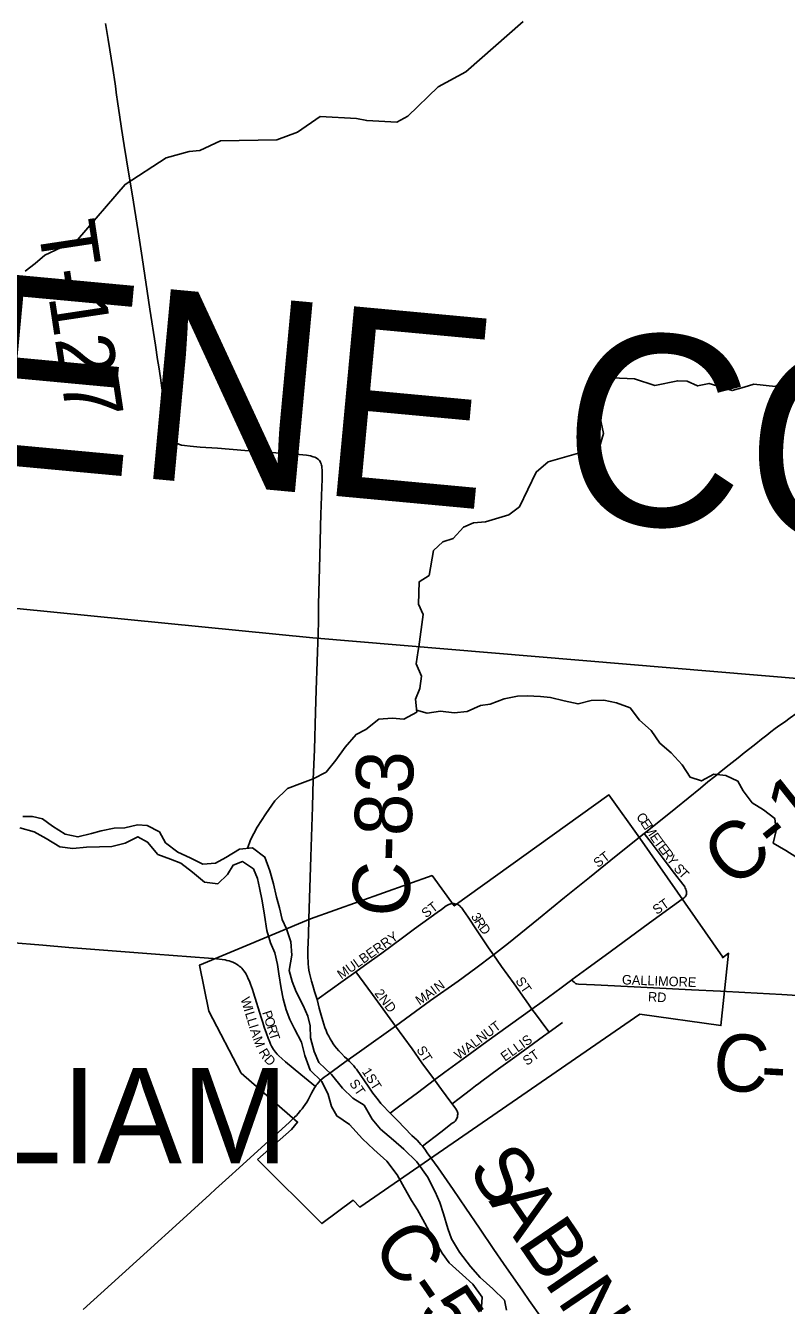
# Model space of a CAD drawing. Extents: x -49 to -8.2, y 9.4 to 23.5.
# Drawn here: x -45.924 to -45.546, y 15.045 to 15.681 of the extents above; entities that cross this region are included whole.
import ezdxf

# ---------------------------------------------------------------- set-up
doc = ezdxf.new("R2010")
doc.units = 0
for name, color, linetype in [('GM_X_Adjacent_County', 7, 'Continuous'), ('GM_X_Adjacent_County_Text', 7, 'Continuous'), ('GM_X_City_Street', 7, 'Continuous'), ('GM_X_City_Street_Text', 7, 'Continuous'), ('GM_X_Corporation', 7, 'Continuous'), ('GM_X_Corporation_Text', 7, 'Continuous'), ('GM_X_County_Road', 7, 'Continuous'), ('GM_X_County_Road_Text', 7, 'Continuous'), ('GM_X_Major_River', 7, 'Continuous'), ('GM_X_Minor_River', 7, 'Continuous'), ('GM_X_State_Route', 7, 'Continuous'), ('GM_X_Township', 7, 'Continuous'), ('GM_X_Township_Road', 7, 'Continuous'), ('GM_X_Township_Road_Text', 7, 'Continuous')]:
    doc.layers.add(name, color=color, linetype=linetype)

msp = doc.modelspace()

# ---------------------------------------------------------------- linework, layer by layer
at = {"layer": 'GM_X_Adjacent_County'}
msp.add_lwpolyline([(-46.28954, 15.42735), (-46.27406, 15.42591), (-46.16919, 15.41553), (-45.78121, 15.37701), (-45.51504, 15.35475), (-44.76178, 15.2786), (-44.52941, 15.25783), (-44.16568, 15.22458), (-44.06357, 15.21525), (-43.87916, 15.1984), (-43.71722, 15.18325)], dxfattribs=at)
at = {"layer": 'GM_X_City_Street'}
for points in [[(-45.6916, 15.21959), (-45.68413, 15.22528), (-45.66921, 15.23738), (-45.65625, 15.24803), (-45.64387, 15.25793), (-45.63065, 15.26869), (-45.61669, 15.2799)], [(-45.59564, 15.2497), (-45.5956, 15.25034), (-45.59568, 15.25096), (-45.59581, 15.25157), (-45.59601, 15.25219), (-45.59626, 15.25272), (-45.59654, 15.25326), (-45.59683, 15.25375), (-45.59743, 15.25462), (-45.60153, 15.26001), (-45.60717, 15.26748), (-45.61315, 15.27541), (-45.61669, 15.2799)], [(-45.65256, 15.20716), (-45.6524, 15.20728), (-45.64514, 15.21262), (-45.63359, 15.22104), (-45.61407, 15.23537), (-45.59787, 15.24715), (-45.59688, 15.24789), (-45.59633, 15.24838), (-45.59597, 15.2488), (-45.59577, 15.24921), (-45.59564, 15.2497)], [(-45.75994, 15.21109), (-45.75561, 15.21423), (-45.74705, 15.22043), (-45.73679, 15.22798), (-45.73078, 15.23239), (-45.71957, 15.24056), (-45.7174, 15.24212), (-45.71499, 15.24382), (-45.71433, 15.24423), (-45.71379, 15.24452), (-45.71326, 15.24477), (-45.71277, 15.24493), (-45.71234, 15.245), (-45.71181, 15.24504), (-45.71123, 15.24504), (-45.71066, 15.24496)], [(-45.6916, 15.21959), (-45.69395, 15.22297), (-45.69968, 15.23144), (-45.70409, 15.23821), (-45.70635, 15.24156), (-45.70704, 15.24249), (-45.70733, 15.24286), (-45.7077, 15.24327), (-45.70823, 15.24381), (-45.70876, 15.24422), (-45.70926, 15.24451), (-45.70987, 15.24475), (-45.71066, 15.24496)], [(-45.77918, 15.19728), (-45.78038, 15.20125), (-45.78132, 15.20433), (-45.78194, 15.20647), (-45.78231, 15.20778), (-45.78264, 15.20914), (-45.78297, 15.21049), (-45.78326, 15.21189), (-45.78344, 15.21343), (-45.78359, 15.21506), (-45.78367, 15.2165), (-45.7837, 15.21781), (-45.78371, 15.21991), (-45.78371, 15.22217), (-45.78349, 15.22933), (-45.7833, 15.23742)], [(-45.8331, 15.21781), (-45.83084, 15.21767), (-45.82911, 15.21754), (-45.82627, 15.21721), (-45.82487, 15.21697), (-45.82392, 15.21677), (-45.82286, 15.21648), (-45.82196, 15.21619), (-45.82097, 15.21582), (-45.82031, 15.21553), (-45.81974, 15.21524), (-45.81916, 15.21491), (-45.81842, 15.21442), (-45.81781, 15.21397), (-45.81711, 15.21339), (-45.81657, 15.21286), (-45.81601, 15.21222), (-45.8155, 15.21154), (-45.81497, 15.21076), (-45.81447, 15.20998), (-45.81392, 15.20901), (-45.81333, 15.20768), (-45.81276, 15.20642), (-45.81222, 15.20501), (-45.81168, 15.20357), (-45.81124, 15.20231), (-45.81069, 15.20065), (-45.80693, 15.18833), (-45.80613, 15.18585), (-45.80539, 15.18355), (-45.80434, 15.18038), (-45.8035, 15.17809), (-45.80268, 15.17605), (-45.80227, 15.17509), (-45.80182, 15.17414), (-45.80136, 15.17332), (-45.80087, 15.17255), (-45.80038, 15.17188), (-45.79977, 15.17112), (-45.79894, 15.17024), (-45.7981, 15.16934), (-45.79672, 15.16806), (-45.79491, 15.16641), (-45.78728, 15.16006), (-45.78365, 15.15712), (-45.77998, 15.15413)], [(-45.74021, 15.18415), (-45.73276, 15.1895), (-45.72275, 15.19689), (-45.70902, 15.20652), (-45.70026, 15.21298), (-45.6916, 15.21959)], [(-45.6724, 15.1926), (-45.67416, 15.19502), (-45.68127, 15.20505), (-45.68747, 15.21376), (-45.6916, 15.21959)], [(-45.77918, 15.19728), (-45.7662, 15.20657), (-45.75994, 15.21109)], [(-45.74021, 15.18415), (-45.7516, 15.19988), (-45.75808, 15.2086), (-45.75994, 15.21109)], [(-45.6724, 15.1926), (-45.66738, 15.19623), (-45.65786, 15.20316), (-45.65256, 15.20716)], [(-45.65256, 15.20716), (-45.65204, 15.20651), (-45.65151, 15.20593), (-45.65114, 15.20556), (-45.65077, 15.20532), (-45.65031, 15.20515), (-45.64933, 15.20499), (-45.64127, 15.20464), (-45.6183, 15.20346), (-45.59314, 15.20214), (-45.57867, 15.20141)], [(-45.76377, 15.16728), (-45.76549, 15.16888), (-45.76709, 15.17048), (-45.76837, 15.17184), (-45.76948, 15.17312), (-45.77034, 15.17419), (-45.77115, 15.1753), (-45.7719, 15.17644), (-45.77265, 15.17772), (-45.77338, 15.17903), (-45.77408, 15.18043), (-45.7747, 15.18187), (-45.7753, 15.18345), (-45.77585, 15.18507), (-45.77637, 15.18674), (-45.77721, 15.18947), (-45.77811, 15.19301), (-45.77918, 15.19728)], [(-45.72086, 15.15736), (-45.71568, 15.1612), (-45.70481, 15.16921), (-45.69483, 15.17638), (-45.6724, 15.1926)], [(-45.66394, 15.18105), (-45.66556, 15.18326), (-45.67015, 15.18952), (-45.6724, 15.1926)], [(-45.76377, 15.16728), (-45.757, 15.17211), (-45.74021, 15.18415)], [(-45.72086, 15.15736), (-45.72707, 15.16593), (-45.73191, 15.17277), (-45.74021, 15.18415)], [(-45.66394, 15.18105), (-45.65718, 15.18598)], [(-45.71205, 15.1454), (-45.70855, 15.14808), (-45.7029, 15.15241), (-45.7004, 15.15437), (-45.6988, 15.1556), (-45.69725, 15.15674), (-45.68901, 15.16281), (-45.68098, 15.16862), (-45.6667, 15.17903), (-45.66394, 15.18105)], [(-45.77998, 15.15413), (-45.77958, 15.1547), (-45.77913, 15.15532), (-45.77837, 15.15623), (-45.77759, 15.15705), (-45.77665, 15.15788), (-45.77565, 15.15867), (-45.77418, 15.15977), (-45.76536, 15.16615), (-45.76377, 15.16728)], [(-45.76377, 15.16728), (-45.76303, 15.16658), (-45.76221, 15.16576), (-45.76151, 15.16502), (-45.76089, 15.16432), (-45.76017, 15.16335), (-45.75966, 15.16264), (-45.75344, 15.15374), (-45.75144, 15.15084), (-45.75021, 15.14913), (-45.74889, 15.14739), (-45.7475, 15.14568), (-45.74591, 15.14393), (-45.74406, 15.14204), (-45.74287, 15.14084)], [(-45.79037, 15.13877), (-45.78947, 15.13971), (-45.78854, 15.1407), (-45.78733, 15.14209), (-45.78659, 15.143), (-45.78585, 15.14398), (-45.78503, 15.14515), (-45.78433, 15.14629), (-45.78363, 15.14752), (-45.78281, 15.14908), (-45.78191, 15.15073), (-45.78109, 15.15224), (-45.78047, 15.15335), (-45.77998, 15.15413)], [(-45.74287, 15.14084), (-45.74007, 15.14293), (-45.73427, 15.14726), (-45.72926, 15.151), (-45.72086, 15.15736)], [(-45.71205, 15.1454), (-45.71279, 15.14638), (-45.71741, 15.1526), (-45.72086, 15.15736)], [(-45.72683, 15.12451), (-45.71768, 15.13141), (-45.71198, 15.13579), (-45.71114, 15.13643), (-45.71061, 15.13692), (-45.71015, 15.1375), (-45.70987, 15.13799), (-45.70962, 15.13853), (-45.70945, 15.13906), (-45.70935, 15.13977), (-45.70929, 15.14034), (-45.70928, 15.14091), (-45.70937, 15.14136), (-45.70954, 15.14177), (-45.70975, 15.14219), (-45.71024, 15.14292), (-45.71076, 15.14367), (-45.71205, 15.1454)], [(-45.74287, 15.14084), (-45.74198, 15.13995), (-45.73901, 15.13695), (-45.73573, 15.13358), (-45.73202, 15.1298)], [(-45.73202, 15.1298), (-45.72951, 15.12734), (-45.72837, 15.12619), (-45.72754, 15.12532), (-45.72683, 15.12451)]]:
    msp.add_lwpolyline(points, dxfattribs=at)
at = {"layer": 'GM_X_Corporation'}
msp.add_lwpolyline([(-45.80878, 15.11774), (-45.79184, 15.13269), (-45.78888, 15.13638), (-45.81682, 15.16078), (-45.8329, 15.19151), (-45.83755, 15.2144), (-45.78239, 15.23744), (-45.72203, 15.25896), (-45.71105, 15.24384), (-45.63422, 15.29901), (-45.61886, 15.27749), (-45.57766, 15.21829), (-45.5777, 15.21809), (-45.57476, 15.22029), (-45.57857, 15.18434), (-45.61881, 15.19), (-45.75795, 15.09414), (-45.76123, 15.09752), (-45.77678, 15.08598)], close=True, dxfattribs=at)
at = {"layer": 'GM_X_County_Road'}
for points in [[(-45.7833, 15.23742), (-45.78229, 15.2682), (-45.78151, 15.29304), (-45.78104, 15.30669), (-45.7805, 15.32157), (-45.77996, 15.34017), (-45.77962, 15.35102), (-45.77913, 15.36529), (-45.77863, 15.37956)], [(-45.61669, 15.2799), (-45.60698, 15.28761), (-45.60102, 15.29247), (-45.58869, 15.30241), (-45.58496, 15.30546), (-45.58154, 15.30821), (-45.57834, 15.31076), (-45.57441, 15.31393), (-45.56995, 15.3175), (-45.56691, 15.31992), (-45.56422, 15.32205), (-45.56124, 15.3244), (-45.5584, 15.32666), (-45.55571, 15.32878), (-45.55372, 15.33032), (-45.55154, 15.33198), (-45.54928, 15.33361), (-45.54702, 15.33525), (-45.54414, 15.33731), (-45.54135, 15.33928), (-45.53814, 15.3415), (-45.53382, 15.34442), (-45.52501, 15.35028), (-45.51027, 15.36047)], [(-45.93186, 15.2257), (-45.91545, 15.22431), (-45.90245, 15.22321), (-45.85938, 15.21988), (-45.8331, 15.21781)], [(-45.57867, 15.20141), (-45.56666, 15.2008), (-45.54821, 15.19974), (-45.51486, 15.19773)], [(-45.72683, 15.12451), (-45.72569, 15.12298), (-45.72442, 15.12113), (-45.71898, 15.11363), (-45.71152, 15.10294), (-45.70531, 15.09364), (-45.69844, 15.08365), (-45.6913, 15.07311), (-45.68662, 15.06614), (-45.67701, 15.05239), (-45.67379, 15.04781), (-45.66774, 15.03917)]]:
    msp.add_lwpolyline(points, dxfattribs=at)
at = {"layer": 'GM_X_Major_River'}
for points in [[(-45.71421, 15.08358), (-45.71628, 15.09079), (-45.71816, 15.09649), (-45.72043, 15.1018), (-45.72439, 15.10921), (-45.72968, 15.11661), (-45.73611, 15.12288), (-45.74122, 15.12744), (-45.74765, 15.13295), (-45.75181, 15.13789), (-45.75578, 15.14473), (-45.76146, 15.14834), (-45.76656, 15.15328), (-45.77205, 15.16012), (-45.77829, 15.16601), (-45.78055, 15.17151), (-45.78243, 15.17834), (-45.78261, 15.18423), (-45.78374, 15.18897), (-45.786, 15.19429), (-45.78959, 15.20112), (-45.79148, 15.20625), (-45.79298, 15.21175), (-45.79165, 15.21933), (-45.7922, 15.22597), (-45.79428, 15.23243), (-45.79654, 15.23717), (-45.79786, 15.24287), (-45.79936, 15.24818), (-45.80087, 15.25482), (-45.80256, 15.26128), (-45.8052, 15.26811), (-45.81126, 15.27267), (-45.8177, 15.27211), (-45.82453, 15.26795), (-45.82965, 15.26511), (-45.8359, 15.26455), (-45.84214, 15.26779), (-45.84839, 15.27064), (-45.85444, 15.27521), (-45.85747, 15.28071), (-45.86352, 15.28376), (-45.86845, 15.28414), (-45.8747, 15.28264), (-45.88001, 15.28245), (-45.88645, 15.28114), (-45.89119, 15.27982), (-45.89801, 15.27812), (-45.90426, 15.27946), (-45.91069, 15.28345), (-45.91561, 15.28706), (-45.92054, 15.28821), (-45.92527, 15.28822)], [(-45.9268, 15.28272), (-45.91979, 15.28062), (-45.91374, 15.27739), (-45.90692, 15.2732), (-45.90048, 15.27243), (-45.89366, 15.27299), (-45.88722, 15.27317), (-45.88116, 15.27335), (-45.87453, 15.27505), (-45.86827, 15.27826), (-45.86335, 15.2756), (-45.85824, 15.26933), (-45.852, 15.26704), (-45.84688, 15.26514), (-45.84102, 15.26058), (-45.83516, 15.25564), (-45.82853, 15.25487), (-45.82359, 15.25941), (-45.82093, 15.26415), (-45.81619, 15.26585), (-45.81071, 15.26224), (-45.80882, 15.25749), (-45.80769, 15.25275), (-45.80638, 15.24629), (-45.80525, 15.23927), (-45.80413, 15.23168), (-45.80224, 15.22542), (-45.80017, 15.22049), (-45.79885, 15.21479), (-45.7981, 15.21005), (-45.79698, 15.20284), (-45.79604, 15.19772), (-45.79453, 15.19221), (-45.79265, 15.18747), (-45.79038, 15.18272), (-45.78698, 15.17608), (-45.78529, 15.16943), (-45.78265, 15.16222), (-45.77679, 15.15652), (-45.77358, 15.15007), (-45.77207, 15.14418), (-45.76943, 15.13944), (-45.76299, 15.13525), (-45.75657, 15.12804), (-45.75089, 15.12272), (-45.74446, 15.11701), (-45.73936, 15.11018), (-45.73596, 15.10391), (-45.73218, 15.09746), (-45.72935, 15.09271), (-45.7267, 15.08796), (-45.72349, 15.08227)], [(-45.72349, 15.08227), (-45.72066, 15.07752), (-45.71707, 15.07126), (-45.71348, 15.06651), (-45.70686, 15.06043), (-45.70175, 15.05587), (-45.69722, 15.04941), (-45.69761, 15.04221)], [(-45.6851, 15.04294), (-45.68604, 15.04788), (-45.69191, 15.05358), (-45.69815, 15.05909), (-45.70287, 15.0646), (-45.70835, 15.07181), (-45.71232, 15.07846), (-45.71421, 15.08358)]]:
    msp.add_lwpolyline(points, dxfattribs=at)
at = {"layer": 'GM_X_Minor_River'}
for points in [[(-45.92421, 15.55925), (-45.91924, 15.56317), (-45.91445, 15.56729), (-45.89824, 15.57486), (-45.87458, 15.60247), (-45.85413, 15.61569), (-45.84271, 15.61877), (-45.8374, 15.61927), (-45.8271, 15.62407), (-45.79921, 15.62466), (-45.78893, 15.62833), (-45.77764, 15.63616), (-45.75964, 15.63516), (-45.75453, 15.63415), (-45.73955, 15.63338), (-45.73402, 15.63635), (-45.71905, 15.65097), (-45.70531, 15.65839), (-45.67675, 15.68346)], [(-45.72863, 15.37266), (-45.72653, 15.38861), (-45.72875, 15.39377), (-45.72842, 15.40497), (-45.72346, 15.40813), (-45.72141, 15.42045), (-45.71662, 15.42476), (-45.71148, 15.4264), (-45.70648, 15.43203), (-45.70152, 15.43425), (-45.69545, 15.43474), (-45.68384, 15.43819), (-45.67867, 15.44212), (-45.67031, 15.45948), (-45.66437, 15.46453), (-45.63887, 15.47179), (-45.63689, 15.47861), (-45.63905, 15.4887), (-45.63936, 15.49478), (-45.63853, 15.50028), (-45.63258, 15.50628), (-45.6214, 15.50575), (-45.61138, 15.50258), (-45.59998, 15.5049), (-45.59524, 15.50465), (-45.59014, 15.50231), (-45.58444, 15.50356), (-45.57291, 15.49999), (-45.56701, 15.50163), (-45.56226, 15.50308), (-45.55146, 15.50199), (-45.54036, 15.51059)], [(-45.81381, 15.27245), (-45.8123, 15.27674), (-45.80896, 15.28295), (-45.80467, 15.28953), (-45.8002, 15.29611), (-45.79383, 15.30227), (-45.78772, 15.30445), (-45.78104, 15.307), (-45.77472, 15.31032), (-45.76987, 15.31632), (-45.76521, 15.3227), (-45.75979, 15.32908), (-45.755, 15.33147), (-45.74846, 15.33668), (-45.74181, 15.33714), (-45.73613, 15.33667), (-45.72962, 15.34018), (-45.73026, 15.34665), (-45.72809, 15.35193), (-45.72722, 15.35799), (-45.72996, 15.36411), (-45.7289, 15.37075), (-45.72863, 15.37266)], [(-45.72971, 15.34117), (-45.7245, 15.33972), (-45.71785, 15.34056), (-45.71103, 15.33988), (-45.70456, 15.34054), (-45.69806, 15.34347), (-45.69312, 15.34415), (-45.68624, 15.3467), (-45.67958, 15.34811), (-45.67483, 15.34823), (-45.66819, 15.34793), (-45.66327, 15.34747), (-45.65647, 15.34584), (-45.64947, 15.34421), (-45.64299, 15.34601), (-45.63673, 15.3461), (-45.63049, 15.34486), (-45.6237, 15.34228), (-45.61906, 15.33613), (-45.61327, 15.3311), (-45.60882, 15.32476), (-45.60321, 15.31992), (-45.59781, 15.31394), (-45.59374, 15.3078), (-45.58827, 15.306), (-45.58214, 15.30932), (-45.57608, 15.30866), (-45.57006, 15.3059), (-45.56748, 15.30111), (-45.56303, 15.29515), (-45.5574, 15.29164), (-45.55178, 15.28737), (-45.55112, 15.28129), (-45.55256, 15.27504), (-45.54636, 15.27133), (-45.54129, 15.26821)]]:
    msp.add_lwpolyline(points, dxfattribs=at)
at = {"layer": 'GM_X_State_Route'}
for points in [[(-45.80497, 15.12535), (-45.79827, 15.13139), (-45.79491, 15.13446), (-45.79284, 15.13637), (-45.79037, 15.13877)], [(-45.83247, 15.10047), (-45.82966, 15.10309), (-45.82299, 15.10911), (-45.81788, 15.11363), (-45.80497, 15.12535)], [(-45.89541, 15.04325), (-45.88133, 15.05595), (-45.86364, 15.07204), (-45.84754, 15.08667), (-45.83247, 15.10047)]]:
    msp.add_lwpolyline(points, dxfattribs=at)
at = {"layer": 'GM_X_Township'}
for points in [[(-43.71722, 15.18325), (-43.87916, 15.1984), (-44.06357, 15.21525), (-44.16568, 15.22458), (-44.52941, 15.25783), (-44.76178, 15.2786), (-45.51504, 15.35475), (-45.78121, 15.37701), (-46.16919, 15.41553), (-46.12789, 16.02951), (-46.09848, 16.46651), (-46.04007, 16.96971), (-46.00808, 17.24521), (-45.75383, 17.22725), (-45.26756, 17.19288), (-44.90793, 17.16748), (-44.90785, 17.16872), (-44.88623, 17.44008), (-44.88572, 17.44739), (-44.35121, 17.40327), (-44.11998, 17.3857), (-43.53715, 17.34141)], [(-44.82058, 14.20392), (-44.15889, 15.08792), (-44.06357, 15.21525), (-44.16568, 15.22458), (-44.52941, 15.25783), (-44.76178, 15.2786), (-45.51504, 15.35475), (-45.78121, 15.37701), (-46.16919, 15.41553), (-46.27406, 15.42591), (-46.28954, 15.42735)]]:
    msp.add_lwpolyline(points, dxfattribs=at)
at = {"layer": 'GM_X_Township_Road'}
msp.add_lwpolyline([(-45.77863, 15.37956), (-45.77853, 15.38495), (-45.7784, 15.39371), (-45.77814, 15.40591), (-45.77781, 15.41771), (-45.77757, 15.42516), (-45.77726, 15.43884), (-45.7772, 15.44255), (-45.77695, 15.44783), (-45.77678, 15.45187), (-45.77666, 15.45604), (-45.7767, 15.46053), (-45.77674, 15.46163), (-45.77684, 15.46241), (-45.77694, 15.46296), (-45.77711, 15.46351), (-45.77739, 15.46419), (-45.7777, 15.46474), (-45.77803, 15.46522), (-45.77849, 15.46567), (-45.77891, 15.46603), (-45.77965, 15.46649), (-45.78033, 15.46683), (-45.78104, 15.46712), (-45.7825, 15.46754), (-45.78348, 15.46772), (-45.78438, 15.46784), (-45.78814, 15.46817), (-45.80201, 15.46923), (-45.80633, 15.46958), (-45.81502, 15.47026), (-45.82862, 15.47132), (-45.83722, 15.47191), (-45.84219, 15.47231), (-45.84499, 15.47262), (-45.8465, 15.4729), (-45.84753, 15.4732), (-45.84851, 15.47365), (-45.84934, 15.4742), (-45.85022, 15.47496), (-45.85088, 15.47574), (-45.85152, 15.4767), (-45.85194, 15.47752), (-45.85229, 15.47848), (-45.85262, 15.47959), (-45.85318, 15.48218), (-45.85434, 15.48908), (-45.85621, 15.50137), (-45.85696, 15.50629), (-45.85781, 15.51181), (-45.85839, 15.51549), (-45.85949, 15.52256), (-45.86221, 15.54037), (-45.86601, 15.5662), (-45.86807, 15.57909), (-45.87105, 15.59779), (-45.87266, 15.6076), (-45.87494, 15.62171), (-45.8763, 15.63031), (-45.87732, 15.63707), (-45.87814, 15.64248), (-45.8789, 15.64811), (-45.87918, 15.64995), (-45.87954, 15.65241), (-45.88069, 15.66009), (-45.88298, 15.67451), (-45.8836, 15.6785), (-45.88421, 15.68249)], dxfattribs=at)

# ---------------------------------------------------------------- texts
at = {"layer": 'GM_X_Adjacent_County_Text'}
msp.add_text('GREENE COUNTY', height=0.094697, rotation=354.68716, dxfattribs=at).set_placement((-46.22828, 15.49024))
at = {"layer": 'GM_X_City_Street_Text'}
for s, height, rotation, p in [('C', 0.00473, 303.71028, (-45.62083, 15.28823)), ('E', 0.00473, 303.72039, (-45.61875, 15.28511)), ('M', 0.00473, 303.68502, (-45.6169, 15.28234)), ('E', 0.00473, 304.67272, (-45.61408, 15.2781)), ('T', 0.00473, 306.67344, (-45.61208, 15.27521)), ('E', 0.00473, 307.14584, (-45.61006, 15.27251)), ('ST', 0.004735, 37.57346, (-45.63962, 15.26261)), ('R', 0.00473, 307.21065, (-45.60804, 15.26984)), ('Y', 0.00473, 307.18471, (-45.60577, 15.26686)), ('S', 0.00473, 309.88889, (-45.60235, 15.26235)), ('T', 0.00473, 314.37325, (-45.59994, 15.2595)), ('ST', 0.004735, 34.68728, (-45.61042, 15.2393)), ('ST', 0.004735, 37.57346, (-45.72504, 15.23761)), ('3', 0.00473, 302.15758, (-45.7029, 15.23862)), ('R', 0.00473, 302.6636, (-45.70132, 15.23611)), ('D', 0.00473, 308.35058, (-45.699, 15.23254)), ('MULBERRY', 0.004735, 35.28861, (-45.76708, 15.20722)), ('GALLIMORE', 0.004735, 357.90998, (-45.62778, 15.20487)), ('2ND', 0.004735, 307.30709, (-45.75086, 15.20035)), ('I', 0.00473, 36.33162, (-45.7206, 15.19965)), ('N', 0.00473, 36.38522, (-45.71892, 15.20089)), ('ST', 0.004735, 304.69079, (-45.68084, 15.20657)), ('W', 0.00473, 287.11139, (-45.81726, 15.19768)), ('M', 0.00473, 33.89215, (-45.72831, 15.19431)), ('A', 0.00473, 35.64664, (-45.72403, 15.19719)), ('RD', 0.004735, 356.98902, (-45.61487, 15.19641)), ('I', 0.00473, 287.09309, (-45.81566, 15.19251)), ('L', 0.00473, 287.12197, (-45.81505, 15.19051)), ('P', 0.00473, 288.00287, (-45.80656, 15.19092)), ('L', 0.00473, 287.11278, (-45.81407, 15.18733)), ('I', 0.00473, 287.10823, (-45.81309, 15.18414)), ('O', 0.00473, 287.99274, (-45.80553, 15.18775)), ('R', 0.00473, 288.00236, (-45.80424, 15.18379)), ('WALNUT', 0.004735, 36.87426, (-45.70878, 15.1672)), ('A', 0.00473, 287.42292, (-45.81247, 15.18213)), ('M', 0.00473, 290.22761, (-45.81114, 15.17791)), ('T', 0.00473, 288.00287, (-45.80308, 15.18022)), ('ELLIS', 0.004735, 35.36457, (-45.68584, 15.16638)), ('R', 0.00473, 301.58497, (-45.8084, 15.17118)), ('ST', 0.004735, 302.73208, (-45.72999, 15.17238)), ('ST', 0.004735, 34.70215, (-45.67494, 15.16427)), ('D', 0.00473, 313.08836, (-45.80581, 15.16716)), ('1ST', 0.004735, 302.28171, (-45.75707, 15.16154)), ('ST', 0.004735, 304.69079, (-45.76337, 15.15569))]:
    msp.add_text(s, height=height, rotation=rotation, dxfattribs=at).set_placement(p)
at = {"layer": 'GM_X_Corporation_Text'}
msp.add_text('PORT WILLIAM', height=0.0473485, rotation=0.00001, dxfattribs=at).set_placement((-46.24734, 15.11591))
at = {"layer": 'GM_X_County_Road_Text'}
for s, height, rotation, p in [('C-83', 0.028409, 88.31175, (-45.73348, 15.23821)), ('C-1', 0.028409, 38.5134, (-45.57277, 15.25173)), ('C', 0.02841, 355.24867, (-45.58332, 15.1528)), ('-', 0.02841, 356.7001, (-45.55928, 15.15081)), ('S', 0.02841, 304.25013, (-45.70488, 15.11285)), ('A', 0.02841, 304.25781, (-45.69409, 15.097)), ('B', 0.02841, 304.25405, (-45.68002, 15.07634)), ('C-5', 0.028409, 304.5582, (-45.75269, 15.07523)), ('I', 0.02841, 304.2568, (-45.66689, 15.05705)), ('N', 0.02841, 304.17606, (-45.66033, 15.04742))]:
    msp.add_text(s, height=height, rotation=rotation, dxfattribs=at).set_placement(p)
at = {"layer": 'GM_X_Township_Road_Text'}
msp.add_text('T-127', height=0.028409, rotation=278.59883, dxfattribs=at).set_placement((-45.918, 15.58226))

doc.saveas('drawing.dxf')
